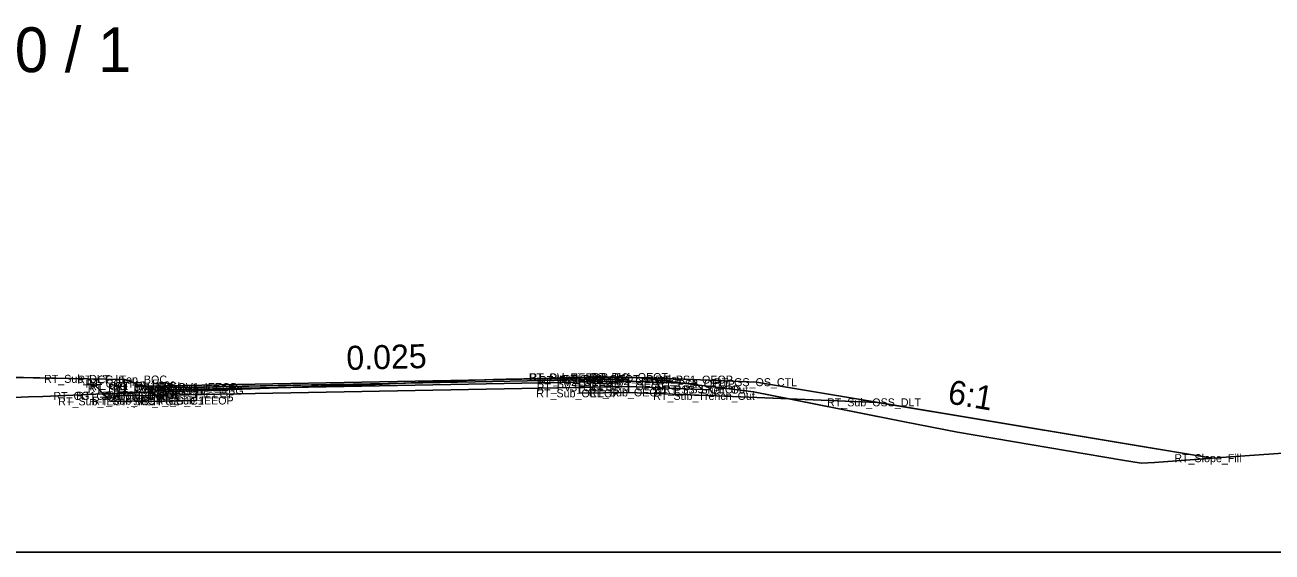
# Model space of a CAD drawing. Extents: x -26 to 2349090, y -10 to 844481.
# Drawn here: x 1154.3 to 1232.2, y 16000 to 16032.9 of the extents above; entities that cross this region are included whole.
import ezdxf

# ---------------------------------------------------------------- set-up
doc = ezdxf.new("R2010")
doc.units = 0
for name, color, linetype in [('Exist CMT Pavement', 7, 'Continuous'), ('Exist Cross Section Cell', 7, 'Continuous'), ('Exist XS Ground Line', 7, 'Continuous'), ('Prop CMT Conc Surface', 7, 'Continuous'), ('Prop CMT Concrete Structures', 7, 'Continuous'), ('Prop CMT Pvmt Course 1', 7, 'Continuous'), ('Prop CMT Pvmt Course 1 CG', 7, 'Continuous'), ('Prop CMT Pvmt Course 1 Wedge', 7, 'Continuous'), ('Prop CMT Pvmt Course 2', 7, 'Continuous'), ('Prop CMT Pvmt Course 2 Wedge', 7, 'Continuous'), ('Prop CMT Pvmt Course 3', 7, 'Continuous'), ('Prop CMT Pvmt Surface', 7, 'Continuous'), ('Prop CMT Pvmt Surface Shoulder', 7, 'Continuous'), ('Prop CMT Pvmt Wedge Surface 1', 7, 'Continuous'), ('Prop CMT Pvmt Wedge Surface 2', 7, 'Continuous'), ('Prop CMT Pvmt Wedge Surface 3', 7, 'Continuous'), ('Prop CMT Shld Paved Course 1', 7, 'Continuous'), ('Prop CMT Shld Paved Course 2', 7, 'Continuous'), ('Prop CMT Shld Paved Course 3', 7, 'Continuous'), ('Prop CMT Slope Grass', 7, 'Continuous'), ('Prop CMT Subgrade Earthwork', 7, 'Continuous'), ('Prop XS Earthwork Shape', 7, 'Continuous'), ('Prop XS SE Text', 7, 'Continuous'), ('Prop XS Side Slope Text', 7, 'Continuous'), ('Scratch_Level_0', 7, 'Continuous')]:
    doc.layers.add(name, color=color, linetype=linetype)

msp = doc.modelspace()

# ---------------------------------------------------------------- linework, layer by layer
at = {"layer": 'Exist CMT Pavement'}
for p, q in [((1176.168, 16010.478), (1178.854, 16010.601)), ((1178.854, 16010.601), (1181.398, 16010.694)), ((1181.398, 16010.694), (1181.614, 16010.703)), ((1181.614, 16010.703), (1181.858, 16010.711)), ((1181.858, 16010.711), (1183.562, 16010.773)), ((1183.562, 16010.773), (1184.347, 16010.796)), ((1184.347, 16010.796), (1185.449, 16010.821)), ((1185.449, 16010.821), (1187.118, 16010.858)), ((1187.118, 16010.858), (1187.77, 16010.877)), ((1187.77, 16010.877), (1188.938, 16010.915)), ((1165.002, 16010.084), (1165.442, 16010.101)), ((1165.442, 16010.101), (1166.014, 16010.125)), ((1166.014, 16010.125), (1166.234, 16010.13)), ((1166.234, 16010.13), (1167.847, 16010.174)), ((1167.847, 16010.174), (1170.107, 16010.257)), ((1170.107, 16010.257), (1170.59, 16010.276)), ((1170.59, 16010.276), (1171.022, 16010.293)), ((1171.022, 16010.293), (1173.34, 16010.391)), ((1173.34, 16010.391), (1174.173, 16010.417)), ((1174.173, 16010.417), (1176.029, 16010.473)), ((1176.029, 16010.473), (1176.105, 16010.475)), ((1176.105, 16010.475), (1176.168, 16010.478))]:
    msp.add_line(p, q, dxfattribs=at)
at = {"layer": 'Exist Cross Section Cell'}
msp.add_line((1150, 16000), (1300, 16000), dxfattribs=at)
at = {"layer": 'Exist XS Ground Line'}
msp.add_lwpolyline([(1154.035, 16009.68), (1154.498, 16009.694), (1155.385, 16009.722), (1156.813, 16009.778), (1158.265, 16009.841), (1159.135, 16009.879), (1159.548, 16009.896), (1161.049, 16009.955), (1162.332, 16009.995), (1164.217, 16010.056), (1164.81, 16010.076), (1165.442, 16010.101), (1166.014, 16010.125), (1167.847, 16010.174), (1170.107, 16010.257), (1170.59, 16010.276), (1171.022, 16010.293), (1173.34, 16010.391), (1174.173, 16010.417), (1176.168, 16010.478), (1178.854, 16010.601), (1181.858, 16010.711), (1183.562, 16010.773), (1184.347, 16010.796), (1185.449, 16010.821), (1187.118, 16010.858), (1187.77, 16010.877), (1188.945, 16010.915), (1189.476, 16010.92), (1189.851, 16010.92), (1191.04, 16010.929), (1191.659, 16010.917), (1192.574, 16010.9), (1194.197, 16010.698), (1199.814, 16010.018), (1209.252, 16008.135), (1212.565, 16007.49), (1222.876, 16005.741), (1224.045, 16005.553), (1224.869, 16005.599), (1229.618, 16005.949), (1239.769, 16006.654)], dxfattribs=at)
at = {"layer": 'Prop CMT Conc Surface'}
for p, q in [((1161.249, 16010.527), (1160.49, 16010.777)), ((1161.25, 16010.36), (1161.249, 16010.527)), ((1162, 16010.374), (1161.25, 16010.36))]:
    msp.add_line(p, q, dxfattribs=at)
at = {"layer": 'Prop CMT Concrete Structures'}
for p, q in [((1161.249, 16010.527), (1160.49, 16010.777)), ((1160.49, 16010.777), (1160.49, 16009.763)), ((1161.25, 16010.36), (1161.249, 16010.527)), ((1160.49, 16009.763), (1162, 16009.791)), ((1162, 16010.374), (1161.25, 16010.36)), ((1162, 16009.791), (1162, 16010.374))]:
    msp.add_line(p, q, dxfattribs=at)
at = {"layer": 'Prop CMT Pvmt Course 1'}
for p, q in [((1162, 16010.374), (1192, 16010.934)), ((1188.94, 16010.752), (1165, 16010.305)), ((1188.94, 16010.627), (1188.94, 16010.752)), ((1192, 16010.684), (1188.94, 16010.627)), ((1192, 16010.934), (1192, 16010.684)), ((1162, 16010.124), (1162, 16010.374)), ((1165, 16010.18), (1162, 16010.124)), ((1165, 16010.305), (1165, 16010.18))]:
    msp.add_line(p, q, dxfattribs=at)
at = {"layer": 'Prop CMT Pvmt Course 1 CG'}
for p, q in [((1159.99, 16009.753), (1159.65, 16009.414)), ((1162, 16009.791), (1159.99, 16009.753)), ((1162, 16009.458), (1162, 16009.791)), ((1159.65, 16009.414), (1162, 16009.458))]:
    msp.add_line(p, q, dxfattribs=at)
at = {"layer": 'Prop CMT Pvmt Course 1 Wedge'}
for p, q in [((1174.173, 16010.476), (1176.029, 16010.511)), ((1176.029, 16010.511), (1176.105, 16010.512)), ((1176.105, 16010.512), (1176.168, 16010.513)), ((1176.168, 16010.513), (1177.47, 16010.538)), ((1177.47, 16010.538), (1176.168, 16010.478)), ((1165, 16010.305), (1165.442, 16010.313)), ((1165, 16010.18), (1165, 16010.305)), ((1165.442, 16010.188), (1165, 16010.18)), ((1165.442, 16010.313), (1166.014, 16010.324)), ((1166.014, 16010.199), (1165.442, 16010.188)), ((1166.014, 16010.324), (1166.234, 16010.328)), ((1166.234, 16010.203), (1166.014, 16010.199)), ((1166.234, 16010.328), (1167.847, 16010.358)), ((1167.847, 16010.233), (1166.234, 16010.203)), ((1167.847, 16010.358), (1170.107, 16010.4)), ((1170.107, 16010.275), (1167.847, 16010.233)), ((1170.107, 16010.4), (1170.59, 16010.409)), ((1170.59, 16010.284), (1170.107, 16010.275)), ((1170.59, 16010.409), (1171.022, 16010.418)), ((1171.021, 16010.293), (1170.59, 16010.284)), ((1171.022, 16010.293), (1171.021, 16010.293)), ((1171.022, 16010.418), (1173.34, 16010.461)), ((1173.34, 16010.391), (1171.022, 16010.293)), ((1173.34, 16010.461), (1174.173, 16010.476)), ((1174.173, 16010.417), (1173.34, 16010.391)), ((1176.029, 16010.473), (1174.173, 16010.417)), ((1176.105, 16010.475), (1176.029, 16010.473)), ((1176.168, 16010.478), (1176.105, 16010.475))]:
    msp.add_line(p, q, dxfattribs=at)
at = {"layer": 'Prop CMT Pvmt Course 2'}
for p, q in [((1188.94, 16010.627), (1192, 16010.684)), ((1188.94, 16010.293), (1188.94, 16010.627)), ((1192, 16010.684), (1192, 16010.35)), ((1162, 16010.124), (1165, 16010.18)), ((1162, 16009.791), (1162, 16010.124)), ((1165, 16009.847), (1162, 16009.791)), ((1165, 16010.18), (1165, 16009.847)), ((1192, 16010.35), (1188.94, 16010.293))]:
    msp.add_line(p, q, dxfattribs=at)
at = {"layer": 'Prop CMT Pvmt Course 2 Wedge'}
for p, q in [((1165, 16010.18), (1165.442, 16010.188)), ((1165, 16010.084), (1165, 16010.18)), ((1165.442, 16010.101), (1165, 16010.084)), ((1165.442, 16010.188), (1166.014, 16010.199)), ((1166.014, 16010.125), (1165.442, 16010.101)), ((1166.014, 16010.199), (1166.234, 16010.203)), ((1166.234, 16010.13), (1166.014, 16010.125)), ((1166.234, 16010.203), (1167.847, 16010.233)), ((1167.847, 16010.174), (1166.234, 16010.13)), ((1167.847, 16010.233), (1170.107, 16010.275)), ((1170.107, 16010.257), (1167.847, 16010.174)), ((1170.107, 16010.275), (1170.59, 16010.284)), ((1170.59, 16010.276), (1170.107, 16010.257)), ((1170.59, 16010.284), (1171.021, 16010.293)), ((1171.021, 16010.293), (1170.59, 16010.276))]:
    msp.add_line(p, q, dxfattribs=at)
at = {"layer": 'Prop CMT Pvmt Course 3'}
for p, q in [((1162, 16009.791), (1165, 16009.847)), ((1162, 16009.416), (1162, 16009.791)), ((1165, 16009.847), (1165, 16009.472)), ((1188.94, 16010.293), (1192, 16010.35)), ((1188.94, 16009.918), (1188.94, 16010.293)), ((1192, 16009.975), (1188.94, 16009.918)), ((1192, 16010.35), (1192, 16009.975)), ((1165, 16009.472), (1162, 16009.416))]:
    msp.add_line(p, q, dxfattribs=at)
at = {"layer": 'Prop CMT Pvmt Surface'}
msp.add_line((1162, 16010.374), (1192, 16010.934), dxfattribs=at)
at = {"layer": 'Prop CMT Pvmt Surface Shoulder'}
msp.add_line((1192, 16010.934), (1196, 16010.774), dxfattribs=at)
at = {"layer": 'Prop CMT Pvmt Wedge Surface 1'}
for p, q in [((1165, 16010.305), (1188.94, 16010.752)), ((1188.94, 16010.752), (1192, 16010.809)), ((1192, 16010.809), (1192, 16010.934)), ((1162, 16010.374), (1162, 16010.249)), ((1162, 16010.249), (1165, 16010.305))]:
    msp.add_line(p, q, dxfattribs=at)
at = {"layer": 'Prop CMT Pvmt Wedge Surface 2'}
for p, q in [((1162, 16010.124), (1192, 16010.684)), ((1192, 16010.684), (1192, 16010.934)), ((1162, 16010.374), (1162, 16010.124))]:
    msp.add_line(p, q, dxfattribs=at)
at = {"layer": 'Prop CMT Pvmt Wedge Surface 3'}
for p, q in [((1192, 16010.35), (1192, 16010.934)), ((1162, 16010.374), (1162, 16009.791)), ((1162, 16009.791), (1192, 16010.35))]:
    msp.add_line(p, q, dxfattribs=at)
at = {"layer": 'Prop CMT Shld Paved Course 1'}
for p, q in [((1192, 16010.934), (1196, 16010.774)), ((1192, 16010.684), (1192, 16010.934)), ((1196.26, 16010.513), (1192, 16010.684)), ((1196, 16010.774), (1196.26, 16010.513))]:
    msp.add_line(p, q, dxfattribs=at)
at = {"layer": 'Prop CMT Shld Paved Course 2'}
for p, q in [((1192, 16010.684), (1196.26, 16010.513)), ((1192, 16010.35), (1192, 16010.684)), ((1196.26, 16010.513), (1196.608, 16010.166)), ((1196.608, 16010.166), (1192, 16010.35))]:
    msp.add_line(p, q, dxfattribs=at)
at = {"layer": 'Prop CMT Shld Paved Course 3'}
for p, q in [((1192, 16010.35), (1196.608, 16010.166)), ((1192, 16009.975), (1192, 16010.35)), ((1197.498, 16009.755), (1192, 16009.975)), ((1196.608, 16010.166), (1197.108, 16010.146)), ((1197.108, 16010.146), (1197.498, 16009.755))]:
    msp.add_line(p, q, dxfattribs=at)
at = {"layer": 'Prop CMT Slope Grass'}
for p, q in [((1160.49, 16010.777), (1147.061, 16011.046)), ((1196, 16010.774), (1200, 16010.614)), ((1196, 16010.774), (1200, 16010.614)), ((1200, 16010.614), (1228.489, 16005.865)), ((1200, 16010.614), (1228.489, 16005.865))]:
    msp.add_line(p, q, dxfattribs=at)
at = {"layer": 'Prop CMT Subgrade Earthwork'}
for p, q in [((1158.242, 16010.822), (1159.65, 16009.414)), ((1188.94, 16009.918), (1188.938, 16010.915)), ((1165, 16009.472), (1165.002, 16010.084)), ((1188.94, 16009.918), (1192, 16009.975)), ((1192, 16009.975), (1197.498, 16009.755)), ((1197.498, 16009.755), (1207.566, 16009.353)), ((1162, 16009.458), (1159.65, 16009.414)), ((1165, 16009.472), (1162, 16009.416)), ((1162, 16009.416), (1162, 16009.458))]:
    msp.add_line(p, q, dxfattribs=at)
at = {"layer": 'Prop XS Earthwork Shape'}
for points in [[(1147.873, 16009.518), (1148.553, 16009.542), (1150, 16009.59), (1151.308, 16009.625), (1152.404, 16009.646), (1154.035, 16009.68), (1154.498, 16009.694), (1155.385, 16009.722), (1156.813, 16009.778), (1158.265, 16009.841), (1159.135, 16009.879), (1159.183, 16009.881), (1158.242, 16010.822), (1147.061, 16011.046), (1135.793, 16010.459), (1135.221, 16009.887), (1142.531, 16009.474), (1143.347, 16009.428), (1145.38, 16009.462), (1145.986, 16009.46), (1146.428, 16009.474)], [(1181.398, 16010.694), (1181.614, 16010.703), (1181.858, 16010.711)], [(1185.449, 16010.821), (1187.118, 16010.858), (1187.77, 16010.877), (1188.938, 16010.915), (1188.938, 16010.877), (1183.864, 16010.782), (1184.347, 16010.796)], [(1188.938, 16010.877), (1188.938, 16010.915), (1189.476, 16010.92), (1189.851, 16010.92), (1191.04, 16010.929), (1191.386, 16010.922)], [(1188.94, 16009.918), (1188.938, 16010.877), (1191.386, 16010.922), (1191.659, 16010.917), (1192.574, 16010.9), (1194.197, 16010.698), (1199.814, 16010.018), (1202.04, 16009.574), (1197.498, 16009.755), (1192, 16009.975)], [(1162.332, 16009.995), (1164.217, 16010.056), (1164.81, 16010.076), (1165.002, 16010.084), (1165, 16009.472), (1162, 16009.416), (1162, 16009.458), (1159.65, 16009.414), (1159.183, 16009.881), (1159.548, 16009.896), (1161.049, 16009.955)], [(1166.014, 16010.125), (1167.847, 16010.174), (1166.234, 16010.13)], [(1174.173, 16010.417), (1176.029, 16010.473), (1176.105, 16010.475), (1176.168, 16010.478)], [(1207.566, 16009.353), (1228.489, 16005.865), (1224.869, 16005.599), (1224.045, 16005.553), (1222.876, 16005.741), (1212.565, 16007.49), (1209.252, 16008.135), (1202.04, 16009.574)]]:
    msp.add_lwpolyline(points, close=True, dxfattribs=at)

# ---------------------------------------------------------------- texts
at = {"layer": 'Exist Cross Section Cell'}
msp.add_text('50+50.00 / 1', height=2.8, dxfattribs=at).set_placement((1140, 16029.986))
at = {"layer": 'Prop XS SE Text'}
msp.add_text('0.025', height=1.5, rotation=1.4321, dxfattribs=at).set_placement((1174.38, 16011.376))
at = {"layer": 'Prop XS Side Slope Text'}
msp.add_text('6:1', height=1.5, rotation=350.53768, dxfattribs=at).set_placement((1211.886, 16009.299))
at = {"layer": 'Scratch_Level_0'}
for s, p in [('RT_Sub_DLT_In', (1155.467, 16010.572)), ('RT_CG_Top_BOC', (1157.549, 16010.527)), ('RT_CG_Top_Face', (1158.052, 16010.277)), ('RT_PV1_Overlay_Null', (1158.205, 16009.999)), ('RT_CG_Top_Gut', (1158.297, 16010.11)), ('RT_PV1_PGL', (1159.933, 16010.124)), ('RT_PV1_IEEOP', (1162.618, 16010.055)), ('RT_Sub Tie Out', (1185.761, 16010.665)), ('RT_PV_OEEOP_EG', (1185.812, 16010.665)), ('RT_PV2_OEEOP', (1186.255, 16010.377)), ('RT_PV3_OEEOP', (1186.255, 16010.043)), ('RT_PV1_OEEOP', (1186.397, 16010.502)), ('RT_PV1_OEOT_Overlay', (1187.898, 16010.559)), ('RT_PV2_OEOT', (1189.532, 16010.434)), ('RT_PV3_OEOT', (1189.532, 16010.1)), ('RT_PV1_OEOT', (1189.673, 16010.684)), ('RT_PS1_OEOP', (1193.689, 16010.524)), ('RT_PS2_OEOP', (1193.808, 16010.263)), ('RT_GS_OS_CTL', (1197.331, 16010.364)), ('RT_CG1_Shelf_In_Med', (1156.049, 16009.503)), ('RT_CG_Bot_BOC1', (1157.474, 16009.513)), ('RT_Sub_IEOT_CG_C1', (1158.469, 16009.208)), ('RT_CG_Bot_IE1', (1159.394, 16009.541)), ('RT_PV2_PGL', (1159.791, 16009.874)), ('RT_PV3_PGL', (1159.791, 16009.541)), ('RT_PV_IEEOP_EG', (1162.037, 16009.834)), ('RT_Sub Tie In', (1162.23, 16009.834)), ('RT_Sub_IEEOP', (1162.453, 16009.222)), ('RT_PV2_IEEOP', (1162.476, 16009.93)), ('RT_PV3_IEEOP', (1162.476, 16009.597)), ('RT_Sub_OEEOP', (1186.231, 16009.668)), ('RT_Sub_OEOT', (1189.508, 16009.725)), ('RT_Sub_Trench_Out', (1193.538, 16009.505)), ('RT_PS3_Shelf_Out', (1193.592, 16009.896)), ('RT_PS3_OEOP', (1194.155, 16009.916)), ('RT_Sub_IEOP_Med', (1156.355, 16009.164)), ('RT_Sub_PGL', (1159.768, 16009.166)), ('RT_Sub_OSS_DLT', (1204.404, 16009.103)), ('RT_Slope_Fill', (1226.107, 16005.615))]:
    msp.add_text(s, height=0.5, dxfattribs=at).set_placement(p)

doc.saveas('drawing.dxf')
